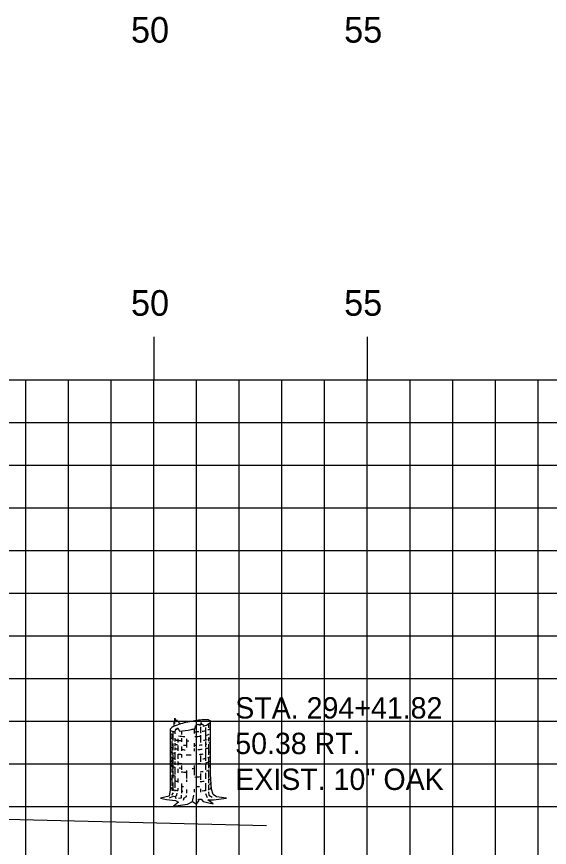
# Model space of a CAD drawing. Extents: x 859352 to 859522, y 366268 to 366378.
# Drawn here: x 859481.92 to 859494.39, y 366286.28 to 366305.75 of the extents above; entities that cross this region are included whole.
import ezdxf

# ---------------------------------------------------------------- set-up
doc = ezdxf.new("R2010")
doc.units = 0
for name, color, linetype in [('D_Text_Monospaced', 7, 'Continuous'), ('H_V ANNOTATION', 7, 'Continuous'), ('MAJOR', 7, 'Continuous'), ('MINOR', 7, 'Continuous'), ('S_Roadway_Centerline', 7, 'Continuous'), ('S_Trees_Decid_NonPay', 7, 'Continuous')]:
    doc.layers.add(name, color=color, linetype=linetype)

msp = doc.modelspace()

# ---------------------------------------------------------------- linework, layer by layer
at = {"layer": 'MAJOR'}
for p, q in [((859485.129, 366298.238), (859485.129, 366297.236)), ((859490.129, 366298.238), (859490.129, 366297.236)), ((859365.129, 366297.236), (859505.129, 366297.236)), ((859365.129, 366297.236), (859505.129, 366297.236)), ((859485.129, 366277.236), (859485.129, 366297.236)), ((859490.129, 366277.236), (859490.129, 366297.236)), ((859365.129, 366292.236), (859505.129, 366292.236)), ((859365.129, 366287.236), (859505.129, 366287.236))]:
    msp.add_line(p, q, dxfattribs=at)
at = {"layer": 'MINOR'}
for p, q in [((859482.129, 366277.236), (859482.129, 366297.236)), ((859483.129, 366277.236), (859483.129, 366297.236)), ((859484.129, 366277.236), (859484.129, 366297.236)), ((859486.129, 366277.236), (859486.129, 366297.236)), ((859487.129, 366277.236), (859487.129, 366297.236)), ((859488.129, 366277.236), (859488.129, 366297.236)), ((859489.129, 366277.236), (859489.129, 366297.236)), ((859491.129, 366277.236), (859491.129, 366297.236)), ((859492.129, 366277.236), (859492.129, 366297.236)), ((859493.129, 366277.236), (859493.129, 366297.236)), ((859494.129, 366277.236), (859494.129, 366297.236)), ((859365.129, 366296.236), (859505.129, 366296.236)), ((859365.129, 366295.236), (859505.129, 366295.236)), ((859365.129, 366294.236), (859505.129, 366294.236)), ((859365.129, 366293.236), (859505.129, 366293.236)), ((859365.129, 366291.236), (859505.129, 366291.236)), ((859365.129, 366290.236), (859505.129, 366290.236)), ((859365.129, 366289.236), (859505.129, 366289.236)), ((859365.129, 366288.236), (859505.129, 366288.236))]:
    msp.add_line(p, q, dxfattribs=at)
at = {"layer": 'S_Roadway_Centerline'}
msp.add_lwpolyline([(859463.938, 366287.704), (859477.165, 366287.052), (859487.767, 366286.791)], dxfattribs=at)
at = {"layer": 'S_Trees_Decid_NonPay'}
for p, q in [((859486.22, 366289.102), (859486.22, 366288.954)), ((859486.339, 366289.085), (859486.339, 366288.784)), ((859486.407, 366289.172), (859486.407, 366289.077)), ((859485.549, 366288.928), (859485.549, 366288.846)), ((859485.576, 366288.998), (859485.576, 366288.781)), ((859485.618, 366288.993), (859485.618, 366288.941)), ((859485.776, 366289.004), (859485.776, 366288.925)), ((859486.073, 366289.056), (859486.073, 366288.949)), ((859486.22, 366288.906), (859486.22, 366288.737)), ((859485.549, 366288.777), (859485.549, 366288.647)), ((859485.576, 366288.712), (859485.576, 366288.56)), ((859485.618, 366288.838), (859485.618, 366288.756)), ((859485.618, 366288.721), (859485.618, 366288.647)), ((859485.689, 366288.82), (859485.689, 366288.733)), ((859485.776, 366288.838), (859485.776, 366288.754)), ((859485.893, 366288.82), (859485.893, 366288.62)), ((859486.073, 366288.721), (859486.073, 366288.634)), ((859486.339, 366288.756), (859486.339, 366288.624)), ((859486.407, 366288.851), (859486.407, 366288.768)), ((859486.407, 366288.699), (859486.407, 366288.447)), ((859485.549, 366288.624), (859485.549, 366288.443)), ((859485.618, 366288.62), (859485.618, 366288.56)), ((859485.618, 366288.507), (859485.618, 366288.326)), ((859485.689, 366288.663), (859485.689, 366288.542)), ((859485.776, 366288.643), (859485.776, 366288.542)), ((859486.073, 366288.599), (859486.073, 366288.529)), ((859486.339, 366288.59), (859486.339, 366288.309)), ((859485.549, 366288.395), (859485.549, 366288.149)), ((859485.576, 366288.455), (859485.576, 366288.377)), ((859485.576, 366288.35), (859485.576, 366288.243)), ((859485.618, 366288.294), (859485.618, 366288.212)), ((859485.689, 366288.466), (859485.689, 366288.352)), ((859485.776, 366288.457), (859485.776, 366288.381)), ((859486.22, 366288.431), (859486.22, 366288.283)), ((859486.407, 366288.365), (859486.407, 366288.134)), ((859485.549, 366288.13), (859485.549, 366288.035)), ((859485.576, 366288.208), (859485.576, 366288.107)), ((859485.618, 366288.159), (859485.618, 366287.988)), ((859485.689, 366288.29), (859485.689, 366288.208)), ((859485.689, 366288.122), (859485.689, 366288.025)), ((859485.776, 366288.196), (859485.776, 366288.099)), ((859486.073, 366288.196), (859486.073, 366287.973)), ((859486.339, 366288.239), (859486.339, 366288.095)), ((859485.547, 366287.982), (859485.548, 366287.722)), ((859485.576, 366288.082), (859485.576, 366287.899)), ((859485.618, 366287.954), (859485.618, 366287.675)), ((859485.893, 366288.082), (859485.893, 366287.895)), ((859486.22, 366288.013), (859486.22, 366287.86)), ((859486.339, 366288.025), (859486.339, 366287.883)), ((859486.407, 366288.064), (859486.407, 366287.903)), ((859485.576, 366287.796), (859485.576, 366287.605)), ((859485.689, 366287.895), (859485.689, 366287.796)), ((859485.776, 366287.774), (859485.776, 366287.55)), ((859485.893, 366287.865), (859485.893, 366287.811)), ((859486.339, 366287.782), (859486.339, 366287.601)), ((859486.407, 366287.887), (859486.407, 366287.782)), ((859486.407, 366287.745), (859486.407, 366287.621)), ((859485.578, 366287.557), (859485.543, 366287.506)), ((859485.549, 366287.683), (859485.549, 366287.609)), ((859485.618, 366287.622), (859485.618, 366287.597)), ((859485.689, 366287.667), (859485.689, 366287.609)), ((859485.893, 366287.636), (859485.893, 366287.545)), ((859486.073, 366287.64), (859486.073, 366287.574)), ((859486.22, 366287.648), (859486.22, 366287.57)), ((859486.34, 366287.541), (859486.381, 366287.445)), ((859485.496, 366287.436), (859485.563, 366287.467)), ((859486.033, 366287.354), (859486.068, 366287.5))]:
    msp.add_line(p, q, dxfattribs=at)
for points in [[(859485.603, 366289.117), (859485.607, 366289.211), (859485.621, 366289.184), (859485.621, 366289.305), (859485.642, 366289.242), (859485.657, 366289.275), (859485.673, 366289.219), (859485.689, 366289.236), (859485.708, 366289.227), (859485.727, 366289.16)], [(859485.508, 366289.036), (859485.508, 366287.624), (859485.485, 366287.475), (859485.282, 366287.432), (859485.422, 366287.397), (859485.64, 366287.378), (859485.71, 366287.335), (859485.588, 366287.246), (859485.92, 366287.29), (859486.033, 366287.354), (859486.126, 366287.294), (859486.181, 366287.372), (859486.173, 366287.409), (859486.235, 366287.411), (859486.286, 366287.354), (859486.519, 366287.302), (859486.391, 366287.391), (859486.523, 366287.393), (859486.832, 366287.43), (859486.593, 366287.461), (859486.515, 366287.519), (859486.476, 366287.64), (859486.459, 366287.994), (859486.459, 366289.227)], [(859485.625, 366288.992), (859485.642, 366289.054), (859485.664, 366289.042), (859485.695, 366289.077), (859485.729, 366288.999)], [(859486.095, 366289.061), (859486.103, 366289.128), (859486.128, 366289.133), (859486.136, 366289.168), (859486.167, 366289.153), (859486.181, 366289.168), (859486.206, 366289.145), (859486.229, 366289.153), (859486.241, 366289.202), (859486.249, 366289.159), (859486.28, 366289.168), (859486.283, 366289.117)], [(859485.626, 366287.467), (859485.669, 366287.502), (859485.677, 366287.55)], [(859486.41, 366287.578), (859486.418, 366287.502), (859486.496, 366287.452)], [(859485.547, 366287.483), (859485.626, 366287.467), (859485.642, 366287.424)], [(859485.773, 366287.502), (859485.767, 366287.432), (859485.704, 366287.42)], [(859485.885, 366287.496), (859485.885, 366287.459), (859485.834, 366287.428), (859485.817, 366287.378)]]:
    msp.add_lwpolyline(points, dxfattribs=at)
for centre, radius, start, end in [((859486.478, 366286.769), 2.507, 93.9457, 101.8277), ((859486.328, 366288.949), 0.322, 71.8277, 93.9457), ((859485.741, 366288.826), 0.322, 109.7098, 131.8277), ((859486.478, 366286.769), 2.507, 101.8277, 109.7098), ((859485.489, 366291.494), 2.507, 288.4719, 289.7098), ((859486.225, 366289.437), 0.322, 289.7098, 311.8277), ((859486.399, 366289.166), 0.0935, 60.604, 71.8277), ((859486.378, 366289.267), 0.0935, 311.8277, 323.0514), ((859486.428, 366289.218), 0.0336, 41.8277, 60.604), ((859486.426, 366289.231), 0.0336, 323.0514, 341.8277), ((859486.436, 366289.225), 0.0237, 27.8832, 41.8277), ((859486.434, 366289.082), 0.0252, 330, 343.9485), ((859486.441, 366289.227), 0.0179, 11.8277, 27.8832), ((859486.441, 366289.227), 0.0179, 355.7722, 11.8277), ((859486.435, 366289.228), 0.0237, 341.8277, 355.7722), ((859486.44, 366289.08), 0.0191, 0, 16.0515), ((859486.44, 366289.08), 0.0191, 343.9485, 0), ((859485.532, 366289.035), 0.0237, 161.8277, 175.7722), ((859485.526, 366289.036), 0.0179, 175.7722, 191.8277), ((859485.526, 366289.036), 0.0179, 191.8277, 207.8832), ((859485.541, 366289.032), 0.0336, 143.0514, 161.8277), ((859485.528, 366288.967), 0.0191, 173.8872, 180), ((859485.528, 366288.967), 0.0191, 180, 196.0515), ((859485.534, 366288.969), 0.0252, 196.0515, 210), ((859485.531, 366289.039), 0.0237, 207.8832, 221.8277), ((859485.543, 366288.974), 0.0356, 210, 228.7494), ((859485.538, 366289.045), 0.0336, 221.8277, 240.604), ((859485.589, 366288.996), 0.0935, 131.8277, 143.0514), ((859485.584, 366289.021), 0.0984, 228.7494, 240), ((859485.568, 366289.097), 0.0935, 240.604, 251.8277), ((859485.698, 366289.218), 0.326, 240, 248.0494), ((859485.639, 366289.314), 0.322, 251.8277, 267.5521), ((859485.984, 366291.228), 2.356, 263.2266, 266.8519), ((859485.489, 366291.494), 2.507, 275.4987, 281.8277), ((859485.489, 366291.494), 2.507, 281.8277, 284.0013), ((859485.984, 366291.341), 2.356, 272.1614, 274.76), ((859485.984, 366291.228), 2.356, 272.6327, 275.758), ((859485.984, 366291.341), 2.356, 276.7201, 278.1032), ((859486.27, 366289.331), 0.326, 278.1032, 282.1964), ((859486.27, 366289.218), 0.326, 282.1964, 299.0901), ((859486.27, 366289.331), 0.326, 291.6757, 300), ((859486.384, 366289.134), 0.0984, 300, 311.2506), ((859486.425, 366289.087), 0.0356, 311.2506, 330), ((859485.528, 366288.866), 0.0191, 173.8872, 180), ((859485.528, 366288.866), 0.0191, 180, 196.0515), ((859485.534, 366288.868), 0.0252, 196.0515, 210), ((859485.528, 366288.763), 0.0191, 173.8872, 180), ((859485.528, 366288.763), 0.0191, 180, 196.0515), ((859485.543, 366288.873), 0.0356, 210, 228.7494), ((859485.584, 366288.92), 0.0984, 228.7494, 240), ((859485.698, 366289.117), 0.326, 240, 248.0494), ((859485.698, 366289.014), 0.326, 255.9618, 261.8968), ((859485.698, 366289.117), 0.326, 260.9146, 261.8968), ((859485.984, 366291.127), 2.356, 261.8968, 264.9353), ((859485.984, 366291.024), 2.356, 261.8968, 262.6162), ((859485.984, 366291.127), 2.356, 267.8019, 269.1881), ((859485.984, 366291.024), 2.356, 275.0054, 276.6587), ((859485.984, 366291.127), 2.356, 277.4481, 278.1032), ((859486.27, 366289.117), 0.326, 278.1032, 289.5833), ((859486.27, 366289.014), 0.326, 282.1964, 288.3169), ((859486.27, 366289.117), 0.326, 296.4281, 300), ((859486.27, 366289.014), 0.326, 296.757, 300), ((859486.384, 366288.92), 0.0984, 300, 311.2506), ((859486.384, 366288.817), 0.0984, 300, 311.2506), ((859486.425, 366288.873), 0.0356, 311.2506, 330), ((859486.425, 366288.77), 0.0356, 311.2506, 330), ((859486.434, 366288.868), 0.0252, 330, 343.9485), ((859486.434, 366288.765), 0.0252, 330, 343.9485), ((859486.44, 366288.866), 0.0191, 0, 16.0515), ((859486.44, 366288.866), 0.0191, 343.9485, 0), ((859486.44, 366288.763), 0.0191, 0, 16.0515), ((859486.44, 366288.763), 0.0191, 343.9485, 0), ((859485.528, 366288.658), 0.0191, 173.8872, 180), ((859485.528, 366288.658), 0.0191, 180, 196.0515), ((859485.534, 366288.66), 0.0252, 196.0515, 210), ((859485.528, 366288.543), 0.0191, 173.8872, 180), ((859485.528, 366288.543), 0.0191, 180, 196.0515), ((859485.534, 366288.545), 0.0252, 196.0515, 210), ((859485.543, 366288.665), 0.0356, 210, 228.7494), ((859485.543, 366288.55), 0.0356, 210, 228.7494), ((859485.584, 366288.712), 0.0984, 228.7494, 240), ((859485.584, 366288.597), 0.0984, 228.7494, 240), ((859485.698, 366288.909), 0.326, 240, 248.0494), ((859485.698, 366288.794), 0.326, 240, 255.9618), ((859485.698, 366288.909), 0.326, 255.9618, 261.8968), ((859485.984, 366290.919), 2.356, 261.8968, 262.8132), ((859485.984, 366290.919), 2.356, 264.9353, 266.9933), ((859485.984, 366291.024), 2.356, 266.0259, 267.8019), ((859485.984, 366291.024), 2.356, 272.1614, 273.4964), ((859485.984, 366290.919), 2.356, 274.3638, 276.7318), ((859486.27, 366288.909), 0.326, 282.1964, 294.8455), ((859486.27, 366288.794), 0.326, 294.8455, 300), ((859486.384, 366288.597), 0.0984, 300, 311.2506), ((859486.425, 366288.55), 0.0356, 311.2506, 330), ((859486.434, 366288.545), 0.0252, 330, 343.9485), ((859486.44, 366288.543), 0.0191, 0, 16.0515), ((859486.44, 366288.543), 0.0191, 343.9485, 0), ((859485.527, 366288.429), 0.0191, 173.8872, 180), ((859485.527, 366288.429), 0.0191, 180, 196.0515), ((859485.533, 366288.43), 0.0252, 196.0515, 210), ((859485.542, 366288.435), 0.0356, 210, 228.7494), ((859485.53, 366288.328), 0.0191, 173.8872, 180), ((859485.53, 366288.328), 0.0191, 180, 196.0515), ((859485.536, 366288.33), 0.0252, 196.0515, 210), ((859485.545, 366288.335), 0.0356, 210, 228.7494), ((859485.583, 366288.483), 0.0984, 228.7494, 240), ((859485.586, 366288.382), 0.0984, 228.7494, 240), ((859485.697, 366288.68), 0.326, 240, 242.9942), ((859485.7, 366288.58), 0.326, 240, 247.5951), ((859485.697, 366288.68), 0.326, 248.1902, 256.0964), ((859485.984, 366290.804), 2.356, 262.8132, 264.9353), ((859485.984, 366290.804), 2.356, 267.586, 270), ((859485.984, 366290.804), 2.356, 270, 270.4422), ((859485.984, 366290.804), 2.356, 275.2089, 277.3412), ((859485.983, 366290.69), 2.356, 277.1385, 278.1032), ((859486.269, 366288.68), 0.326, 278.1032, 282.3301), ((859486.273, 366288.58), 0.326, 283.0921, 300), ((859486.269, 366288.68), 0.326, 292.1344, 300), ((859486.383, 366288.483), 0.0984, 300, 311.2506), ((859486.425, 366288.435), 0.0356, 311.2506, 330), ((859486.434, 366288.43), 0.0252, 330, 343.9485), ((859486.44, 366288.429), 0.0191, 0, 16.0515), ((859486.44, 366288.429), 0.0191, 343.9485, 0), ((859486.443, 366288.328), 0.0191, 0, 16.0515), ((859485.528, 366288.224), 0.0191, 173.8872, 180), ((859485.528, 366288.224), 0.0191, 180, 196.0515), ((859485.534, 366288.225), 0.0252, 196.0515, 210), ((859485.528, 366288.133), 0.0191, 173.8872, 180), ((859485.543, 366288.23), 0.0356, 210, 228.7494), ((859485.584, 366288.278), 0.0984, 228.7494, 240), ((859485.698, 366288.475), 0.326, 240, 242.8475), ((859485.698, 366288.475), 0.326, 248.0494, 255.9618), ((859485.986, 366290.59), 2.356, 262.7545, 265.0266), ((859485.984, 366290.485), 2.356, 263.572, 264.9353), ((859485.984, 366290.485), 2.356, 270.9946, 272.1614), ((859485.986, 366290.59), 2.356, 273.1471, 275.6557), ((859486.27, 366288.475), 0.326, 294.8455, 300), ((859486.384, 366288.278), 0.0984, 300, 311.2506), ((859486.425, 366288.23), 0.0356, 311.2506, 330), ((859486.434, 366288.225), 0.0252, 330, 343.9485), ((859486.44, 366288.224), 0.0191, 0, 16.0515), ((859486.44, 366288.224), 0.0191, 343.9485, 0), ((859485.532, 366287.904), 0.0191, 173.8872, 180), ((859485.532, 366287.904), 0.0191, 180, 196.0515), ((859485.698, 366288.271), 0.326, 248.0494, 255.9618), ((859485.984, 366290.394), 2.356, 264.7274, 267.8019), ((859485.984, 366290.281), 2.356, 272.531, 275.758), ((859485.984, 366290.394), 2.356, 275.5135, 277.4157), ((859486.27, 366288.384), 0.326, 286.0817, 298.061), ((859486.444, 366287.904), 0.0191, 0, 16.0515), ((859486.444, 366287.904), 0.0191, 343.9485, 0), ((859485.538, 366287.906), 0.0252, 196.0515, 210), ((859485.547, 366287.911), 0.0356, 210, 228.7494), ((859485.588, 366287.959), 0.0984, 228.7494, 240), ((859485.707, 366288.045), 0.326, 240, 246.3456), ((859485.702, 366288.156), 0.326, 255.2259, 261.8968), ((859485.988, 366290.166), 2.356, 261.8968, 262.7137), ((859485.993, 366290.055), 2.356, 264.7171, 265.8136), ((859485.993, 366290.055), 2.356, 273.1842, 275.0911), ((859485.988, 366290.166), 2.356, 275.5148, 277.7774), ((859486.274, 366288.156), 0.326, 294.0625, 300), ((859486.279, 366288.045), 0.326, 298.0903, 300), ((859486.388, 366287.959), 0.0984, 300, 311.2506), ((859486.393, 366287.848), 0.0984, 300, 311.2506), ((859486.43, 366287.911), 0.0356, 311.2506, 330), ((859486.434, 366287.801), 0.0356, 311.2506, 330), ((859486.439, 366287.906), 0.0252, 330, 343.9485), ((859486.443, 366287.796), 0.0252, 330, 343.9485), ((859486.449, 366287.794), 0.0191, 0, 16.0515), ((859486.449, 366287.794), 0.0191, 343.9485, 0), ((859485.542, 366287.684), 0.0191, 173.8872, 180), ((859485.542, 366287.684), 0.0191, 180, 196.0515), ((859485.548, 366287.685), 0.0252, 196.0515, 210), ((859485.557, 366287.691), 0.0356, 210, 228.7494), ((859485.598, 366287.738), 0.0984, 228.7494, 240), ((859485.712, 366287.935), 0.326, 245.2906, 261.8968), ((859485.998, 366289.945), 2.356, 261.8968, 262.4597), ((859485.998, 366289.945), 2.356, 264.5833, 265.4449), ((859485.998, 366289.945), 2.356, 276.4667, 278.1032), ((859486.285, 366287.935), 0.326, 278.1032, 279.6166), ((859486.285, 366287.935), 0.326, 292.0839, 300), ((859486.398, 366287.738), 0.0984, 300, 311.2506), ((859486.44, 366287.691), 0.0356, 311.2506, 330), ((859486.449, 366287.685), 0.0252, 330, 343.9485), ((859486.455, 366287.684), 0.0191, 0, 16.0515), ((859486.455, 366287.684), 0.0191, 343.9485, 0)]:
    msp.add_arc(centre, radius, start, end, dxfattribs=at)

# ---------------------------------------------------------------- texts
at = {"layer": 'D_Text_Monospaced'}
for s, height, p in [('STA. 294+41.82', 0.49998, (859487.036, 366289.298)), ('50.38 RT.', 0.5, (859487.036, 366288.464)), ('EXIST. 10" OAK', 0.49998, (859487.036, 366287.624))]:
    msp.add_text(s, height=height, dxfattribs=at).set_placement(p)
at = {"layer": 'H_V ANNOTATION'}
for s, p in [('50', (859484.594, 366305.136)), ('55', (859489.586, 366305.136)), ('50', (859484.594, 366298.736)), ('55', (859489.586, 366298.736))]:
    msp.add_text(s, height=0.6, dxfattribs=at).set_placement(p)

doc.saveas('drawing.dxf')
